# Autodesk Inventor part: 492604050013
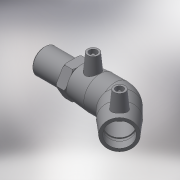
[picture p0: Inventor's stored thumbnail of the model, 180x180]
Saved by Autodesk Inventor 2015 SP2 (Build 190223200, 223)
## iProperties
Created: 2017-06
Part Number: 492604050013
Material: Generic
Description: PLASSON 45° ELBOW TRANSITION MALE 50-1.1/4"
Document SubType Name: Modeling
Designer: KIM
Mass: 291.296 g
Surface Area: 613.206 cm^2
Volume: 291.296 cm^3
Density: 1 g/cm^3
Appearance: Default
Author: KIM
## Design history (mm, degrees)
derived "492604.ipt"
feature "Solid1::492604.ipt"
tag "TaggingFeature1"
body "Solid1"
other parameters: "d2" = 67, "d4" = 31.25, "d5" = 60.3, "d8" = 168 deg, "d10" = 19.6, "d11" = 6.53333, "d29" = 51, "d30" = 15, "d31" = 43.75, "d34" = 5 deg, "d41" = 4, "d42" = 14, "d43" = 0, "d50" = 32.5, "d51" = 19.6, "d52" = 50.47, "d54" = 135 deg, "d86" = 30.15, "d87" = 135 deg, "d88" = 125, "d90" = 49, "d91" = 0, "d92" = 49, "d93" = 0, "d101" = 3, "d102" = 0, "d107" = 0.1, "d108" = 38, "d109" = 41.91, "d110" = 36, "d111" = 9, "d112" = 67, "d113" = 29.337, "d114" = 32.4, "d116" = 2.01, "d122" = 0, "d123" = 2.0955, "L_" = 161, "L_1" = 49, "D_" = 38, "A_" = 51, "d_2" = 12, "L_2" = 36, "R_" = 41.91, "D_1" = 67
